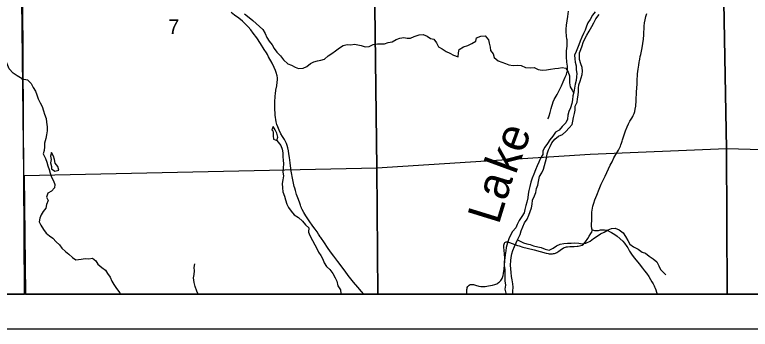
# Model space of a CAD drawing. Extents: x 0 to 34, y 0 to 22.
# Drawn here: x 4.117 to 6.214, y 14.287 to 15.182 of the extents above; entities that cross this region are included whole.
import ezdxf

# ---------------------------------------------------------------- set-up
doc = ezdxf.new("R2010")
doc.units = 0
for name, color, linetype in [('GM_X_County_Road_Text', 7, 'Continuous'), ('GM_X_Interchange_Ramps', 7, 'Continuous'), ('GM_X_Minor_River_Text', 7, 'Continuous'), ('GM_X_State_Location', 7, 'Continuous'), ('GM_X_State_Route', 7, 'Continuous'), ('GM_X_State_Shield', 7, 'Continuous'), ('GM_X_Unincorporated_Location', 7, 'Continuous'), ('SH_Data', 7, 'Continuous')]:
    doc.layers.add(name, color=color, linetype=linetype)

msp = doc.modelspace()

# ---------------------------------------------------------------- linework, layer by layer
at = {"layer": 'GM_X_County_Road_Text'}
for points in [[(4.772, 15.1846), (4.785, 15.1741), (4.7953, 15.1651), (4.8049, 15.1572), (4.8144, 15.1485), (4.8244, 15.1399), (4.8305, 15.1286), (4.8356, 15.1168), (4.8417, 15.1066), (4.8505, 15.0961), (4.8567, 15.0859), (4.864, 15.075), (4.8743, 15.0648), (4.8827, 15.0535), (4.8957, 15.0418), (4.906, 15.0378), (4.9167, 15.0321), (4.9262, 15.0288), (4.9387, 15.0297), (4.9492, 15.0347), (4.9598, 15.0428), (4.9696, 15.0481), (4.9798, 15.0509), (4.9896, 15.0525), (4.9998, 15.0552), (5.0103, 15.0644), (5.0205, 15.0713), (5.031, 15.079), (5.0431, 15.0875), (5.0533, 15.094), (5.0646, 15.0967), (5.0752, 15.0965), (5.0851, 15.0981), (5.0949, 15.0959), (5.1044, 15.094), (5.1162, 15.09), (5.1275, 15.0916), (5.1389, 15.0966), (5.1506, 15.099), (5.1612, 15.0987), (5.1711, 15.0991), (5.1809, 15.1023), (5.1926, 15.105), (5.2043, 15.1108), (5.2149, 15.1147), (5.2258, 15.1167), (5.2353, 15.1149), (5.2448, 15.1146), (5.2557, 15.1196), (5.2697, 15.125), (5.2815, 15.1255), (5.2925, 15.1203), (5.302, 15.1139), (5.3115, 15.1121), (5.3188, 15.1015), (5.325, 15.0906), (5.3356, 15.0846), (5.3467, 15.0775), (5.3573, 15.0722), (5.3672, 15.067), (5.3813, 15.0618), (5.3823, 15.0732), (5.3841, 15.0831), (5.3958, 15.09), (5.4087, 15.0939), (5.4196, 15.0997), (5.4313, 15.1062), (5.4327, 15.1161), (5.4456, 15.1212), (5.4581, 15.122), (5.4673, 15.1103), (5.4689, 15.1005), (5.472, 15.0899), (5.4728, 15.0804), (5.4805, 15.0702), (5.4836, 15.0604), (5.4951, 15.0506), (5.5156, 15.0432), (5.5251, 15.0391), (5.5377, 15.0369), (5.5498, 15.0382), (5.5608, 15.0368), (5.5733, 15.0316), (5.5858, 15.0305)], [(4.1378, 14.9976), (4.1377, 14.9995), (4.124, 15.0077), (4.1122, 15.0152), (4.1011, 15.028), (4.0953, 15.042), (4.0891, 15.0564), (4.0836, 15.0681), (4.0767, 15.0794), (4.0683, 15.0907), (4.0564, 15.1005), (4.0442, 15.1083), (4.0336, 15.1131), (4.0229, 15.1172), (4.0107, 15.1228), (4.003, 15.1334), (3.9973, 15.1454), (3.993, 15.1587), (3.9891, 15.1708)], [(5.5858, 15.0305), (5.5976, 15.0314), (5.6094, 15.0254), (5.62, 15.024), (5.6325, 15.0252), (5.6442, 15.0272), (5.6567, 15.0288), (5.6669, 15.0301), (5.6771, 15.0317), (5.6874, 15.0298), (5.6947, 15.0181), (5.6986, 15.0083), (5.6983, 14.9984), (5.698, 14.9878), (5.7004, 14.9768), (5.7054, 14.9666), (5.7101, 14.9603)], [(4.1377, 14.9995), (4.1535, 14.9962), (4.1634, 14.9856), (4.1696, 14.9747), (4.1757, 14.9645), (4.18, 14.9535), (4.1835, 14.9425), (4.1897, 14.9312), (4.1955, 14.9203), (4.1986, 14.9085), (4.2021, 14.8983), (4.206, 14.8862), (4.2076, 14.876), (4.2093, 14.8627), (4.2097, 14.8513), (4.2072, 14.8399), (4.2054, 14.8297), (4.2021, 14.8164), (4.2014, 14.8054), (4.2008, 14.7951), (4.1982, 14.7856), (4.2044, 14.7728), (4.2083, 14.7618), (4.211, 14.7516), (4.2149, 14.741), (4.2177, 14.7304), (4.2219, 14.7194), (4.2277, 14.7092), (4.2312, 14.6986), (4.2302, 14.6891), (4.2215, 14.6796), (4.211, 14.6738), (4.2073, 14.6624), (4.2119, 14.6526), (4.2079, 14.6419), (4.2053, 14.6316), (4.1982, 14.6221), (4.1926, 14.6122), (4.1885, 14.6027), (4.1867, 14.5928), (4.1913, 14.5826), (4.199, 14.5701), (4.2067, 14.56), (4.2163, 14.5524), (4.2258, 14.5461), (4.2346, 14.5359), (4.2441, 14.5269), (4.2507, 14.5171), (4.2614, 14.5084), (4.2713, 14.5005), (4.2816, 14.4908), (4.2915, 14.4844), (4.3059, 14.4864), (4.3176, 14.4884), (4.3282, 14.4874), (4.3381, 14.4886), (4.3476, 14.4815), (4.3542, 14.4717), (4.3656, 14.4623), (4.3759, 14.4551), (4.3813, 14.4453), (4.389, 14.4348), (4.3936, 14.4234), (4.3998, 14.4136), (4.4074, 14.4027), (4.4167, 14.3906), (4.4188, 14.3866)], [(4.864, 14.8242), (4.8751, 14.8099), (4.8794, 14.7989), (4.8814, 14.7883), (4.8811, 14.7777), (4.8823, 14.7678), (4.8828, 14.7576), (4.8821, 14.7458), (4.8811, 14.734), (4.8827, 14.7231), (4.8809, 14.7117), (4.8795, 14.7018), (4.8804, 14.6889), (4.8809, 14.6775), (4.8859, 14.665), (4.8883, 14.6548), (4.8929, 14.6427), (4.8976, 14.6329), (4.9045, 14.6223), (4.9137, 14.6125), (4.9255, 14.605), (4.9369, 14.5941), (4.9454, 14.584), (4.9549, 14.5749), (4.9546, 14.5632), (4.9581, 14.5533), (4.9655, 14.5397), (4.9724, 14.5269), (4.9782, 14.5167), (4.9832, 14.5061), (4.989, 14.4963), (4.9951, 14.4865), (4.9994, 14.4755), (5.0056, 14.465), (5.0155, 14.4571), (5.0235, 14.445), (5.0301, 14.4329), (5.0347, 14.4231), (5.0383, 14.4106), (5.0459, 14.3989), (5.0468, 14.3883), (5.0476, 14.3866)], [(5.5498, 14.5411), (5.5669, 14.533), (5.5764, 14.5297), (5.5858, 14.5282), (5.5957, 14.5245), (5.6079, 14.5212), (5.6178, 14.519), (5.6288, 14.5145), (5.6406, 14.5116), (5.6515, 14.5174), (5.6613, 14.5243), (5.6719, 14.5286), (5.6825, 14.5305), (5.693, 14.5318), (5.7033, 14.5319), (5.7135, 14.5323), (5.7245, 14.5313), (5.734, 14.5298), (5.7453, 14.5318), (5.757, 14.5372), (5.7668, 14.5449), (5.777, 14.5511), (5.7868, 14.5583), (5.7973, 14.5634), (5.8083, 14.5699), (5.8181, 14.5734), (5.8287, 14.5742), (5.8397, 14.5698), (5.8512, 14.5608), (5.8577, 14.551), (5.865, 14.5396), (5.8704, 14.5291), (5.8807, 14.5208), (5.894, 14.5145), (5.9051, 14.5062), (5.9146, 14.5036), (5.9257, 14.4946), (5.9367, 14.4875), (5.9474, 14.4785), (5.9528, 14.4675), (5.9575, 14.4566), (5.967, 14.4468), (5.9724, 14.4419)], [(4.6398, 14.3866), (4.6356, 14.3951), (4.6313, 14.408), (4.6282, 14.4197), (4.6269, 14.433), (4.6284, 14.4425), (4.6294, 14.4527), (4.6282, 14.4622), (4.6307, 14.4728), (4.6304, 14.4728)]]:
    msp.add_lwpolyline(points, dxfattribs=at)
at = {"layer": 'GM_X_Interchange_Ramps'}
for points in [[(5.1119, 14.3866), (5.1054, 14.3945), (5.0952, 14.4062), (5.083, 14.4203), (5.0714, 14.4348), (5.0677, 14.4398), (5.0585, 14.4522), (5.0382, 14.4797), (5.0268, 14.4944), (5.0174, 14.5068), (5.0083, 14.5194), (4.9995, 14.5322), (4.9893, 14.5475), (4.9875, 14.5501), (4.9843, 14.5548), (4.9825, 14.5576), (4.9787, 14.5636), (4.9728, 14.5717), (4.9669, 14.5799), (4.956, 14.5955), (4.9469, 14.6091), (4.9411, 14.6189), (4.9361, 14.6278), (4.9346, 14.6311), (4.934, 14.6325), (4.9326, 14.636), (4.9312, 14.6399), (4.9294, 14.6455), (4.9257, 14.6555), (4.9205, 14.6701), (4.9168, 14.682), (4.9151, 14.688), (4.9136, 14.6931), (4.9113, 14.7024), (4.9092, 14.7121), (4.905, 14.7361), (4.9018, 14.7604), (4.8998, 14.7759), (4.8984, 14.7857), (4.897, 14.7946), (4.8954, 14.803), (4.8936, 14.8094), (4.8913, 14.8155), (4.889, 14.8206), (4.8854, 14.8269), (4.8802, 14.8351), (4.8753, 14.8432), (4.8703, 14.8537), (4.8668, 14.8625), (4.8642, 14.8694), (4.8624, 14.8771), (4.8612, 14.8833), (4.8602, 14.8897), (4.8594, 14.8959), (4.8589, 14.903), (4.8585, 14.9115), (4.8583, 14.914), (4.8582, 14.926), (4.8586, 14.9383), (4.859, 14.9445), (4.8594, 14.9507), (4.8599, 14.9568), (4.8612, 14.9673), (4.8636, 14.9795), (4.8652, 14.9896), (4.8656, 14.9969), (4.8656, 14.9998), (4.8656, 15.0024), (4.865, 15.0074), (4.8624, 15.0174), (4.8606, 15.0227), (4.8566, 15.0314), (4.8504, 15.0441), (4.8407, 15.0622), (4.837, 15.0684), (4.8341, 15.0733), (4.8283, 15.083), (4.8178, 15.0994), (4.8069, 15.1159), (4.797, 15.1295), (4.7902, 15.1388), (4.7825, 15.1474), (4.7758, 15.154), (4.7665, 15.1633), (4.7554, 15.1723), (4.7437, 15.1804), (4.7343, 15.1878)], [(5.6367, 14.8857), (5.638, 14.8885), (5.6403, 14.8943), (5.643, 14.9032), (5.6459, 14.9152), (5.6476, 14.9212), (5.6496, 14.9276), (5.6519, 14.934), (5.6545, 14.9404), (5.663, 14.9549), (5.6696, 14.9678), (5.6753, 14.9794), (5.6805, 14.9906), (5.6862, 15.0036), (5.6893, 15.0117), (5.6911, 15.017), (5.6924, 15.0211), (5.693, 15.026), (5.6924, 15.035), (5.6907, 15.0471), (5.6897, 15.0618), (5.6896, 15.0728), (5.69, 15.0791), (5.6915, 15.0924), (5.6918, 15.104), (5.6915, 15.108), (5.6913, 15.1104), (5.691, 15.113), (5.6897, 15.1212), (5.6885, 15.1343), (5.6885, 15.1379), (5.6886, 15.1409), (5.6899, 15.1523), (5.6917, 15.164), (5.6934, 15.1767), (5.6955, 15.1918)], [(5.764, 14.5698), (5.7624, 14.5727), (5.7616, 14.5753), (5.7614, 14.5775), (5.7613, 14.5847), (5.7617, 14.5971), (5.7618, 14.6094), (5.7619, 14.6155), (5.7621, 14.6196), (5.7627, 14.6255), (5.7634, 14.6308), (5.7648, 14.6368), (5.7674, 14.6458), (5.7707, 14.6545), (5.7761, 14.6682), (5.783, 14.6857), (5.7889, 14.6996), (5.7924, 14.7069), (5.7997, 14.7223), (5.8046, 14.7326), (5.8098, 14.7435), (5.8146, 14.7536), (5.8195, 14.7634), (5.8249, 14.7743), (5.8377, 14.796), (5.8411, 14.8024), (5.8432, 14.8074), (5.8449, 14.8116), (5.8465, 14.8167), (5.8481, 14.8219), (5.8491, 14.8253), (5.8503, 14.8289), (5.8547, 14.8425), (5.8578, 14.8512), (5.8625, 14.8627), (5.8664, 14.871), (5.8707, 14.8791), (5.8755, 14.887), (5.8787, 14.8923), (5.8802, 14.8951), (5.8826, 14.9008), (5.8846, 14.9067), (5.8859, 14.9127), (5.8871, 14.922), (5.8881, 14.9375), (5.8896, 14.9623), (5.8908, 14.9839), (5.8912, 14.99), (5.8915, 14.9961), (5.892, 15.0095), (5.8925, 15.0139), (5.8942, 15.0272), (5.8959, 15.0378), (5.8973, 15.0468), (5.8979, 15.0504), (5.8988, 15.0554), (5.9001, 15.063), (5.9016, 15.069), (5.9052, 15.0872), (5.9073, 15.0995), (5.909, 15.1118), (5.9101, 15.1242), (5.9111, 15.149), (5.9121, 15.1583), (5.9138, 15.1674), (5.9159, 15.1765), (5.9186, 15.1854)], [(5.4058, 14.3866), (5.4058, 14.3962), (5.406, 14.3996), (5.4063, 14.4024), (5.407, 14.4055), (5.4082, 14.4083), (5.4101, 14.4107), (5.4126, 14.4125), (5.4154, 14.4137), (5.4184, 14.4142), (5.4215, 14.4142), (5.4246, 14.4137), (5.4306, 14.4121), (5.4396, 14.4095), (5.4457, 14.4084), (5.4518, 14.408), (5.458, 14.4084), (5.4671, 14.4099), (5.4792, 14.4123), (5.4852, 14.414), (5.4881, 14.415), (5.4909, 14.4163), (5.4936, 14.4177), (5.4962, 14.4194), (5.4987, 14.4213), (5.5009, 14.4234), (5.5029, 14.4257), (5.5047, 14.4282), (5.5062, 14.4309), (5.5075, 14.4337), (5.5085, 14.4366), (5.5094, 14.4396), (5.5106, 14.4457), (5.5122, 14.458), (5.5134, 14.4703), (5.5139, 14.4797), (5.5139, 14.489), (5.5131, 14.5014), (5.5122, 14.5106), (5.511, 14.5199), (5.5108, 14.523), (5.5109, 14.5261), (5.5116, 14.5291), (5.5131, 14.5317), (5.5144, 14.5333), (5.5162, 14.5344), (5.5182, 14.535), (5.5213, 14.5353), (5.5243, 14.5349), (5.5273, 14.534), (5.5505, 14.5251), (5.5549, 14.5237), (5.5653, 14.5207), (5.5776, 14.5175), (5.5973, 14.5123), (5.6313, 14.5034), (5.6374, 14.502), (5.6404, 14.5015), (5.6438, 14.5011), (5.6466, 14.5012), (5.6497, 14.5014), (5.6527, 14.502), (5.6555, 14.5027), (5.6582, 14.5036), (5.6617, 14.5053), (5.668, 14.5088), (5.6759, 14.5143), (5.6802, 14.5173), (5.683, 14.5191), (5.6868, 14.5204), (5.6898, 14.521), (5.6929, 14.5215), (5.699, 14.5221), (5.705, 14.5224), (5.708, 14.5224), (5.7111, 14.5225), (5.7201, 14.5229), (5.7231, 14.5232), (5.7271, 14.5237), (5.7308, 14.5247), (5.7346, 14.5262), (5.7382, 14.5287), (5.7435, 14.5358), (5.7507, 14.5454), (5.7547, 14.5517), (5.7594, 14.5591), (5.761, 14.5618), (5.7618, 14.5632), (5.7624, 14.5645), (5.7631, 14.5663), (5.764, 14.5698)], [(5.764, 14.5698), (5.7663, 14.569), (5.7696, 14.5681), (5.7748, 14.5676), (5.7777, 14.5676), (5.7791, 14.5678), (5.7808, 14.568), (5.7836, 14.5686), (5.7866, 14.5692), (5.7885, 14.5694), (5.7906, 14.5696), (5.7943, 14.5697), (5.7982, 14.5694), (5.8043, 14.5682), (5.8093, 14.5664), (5.8108, 14.5658), (5.8125, 14.565), (5.8182, 14.5619), (5.8272, 14.5567), (5.8344, 14.5516), (5.8502, 14.537), (5.8546, 14.5314), (5.8619, 14.5224), (5.8649, 14.5181), (5.8695, 14.5089), (5.873, 14.5036), (5.8773, 14.4978), (5.8838, 14.489), (5.8973, 14.4728), (5.9067, 14.4603), (5.9125, 14.4529), (5.918, 14.4459), (5.9244, 14.4365), (5.9295, 14.4286), (5.9332, 14.422), (5.9366, 14.4156), (5.9392, 14.4105), (5.9408, 14.4073), (5.9424, 14.4032), (5.944, 14.3985), (5.9461, 14.392), (5.9477, 14.3866)]]:
    msp.add_lwpolyline(points, dxfattribs=at)
at = {"layer": 'GM_X_Minor_River_Text'}
for points in [[(4.864, 14.8242), (4.8666, 14.8337), (4.8638, 14.8443), (4.8592, 14.8541), (4.8534, 14.8639), (4.8497, 14.8544), (4.8528, 14.851)], [(4.8528, 14.851), (4.8532, 14.8469), (4.854, 14.8374), (4.8545, 14.8275), (4.864, 14.8242)], [(4.2398, 14.7495), (4.2322, 14.7593), (4.2302, 14.7696), (4.2274, 14.7794), (4.2213, 14.7896), (4.2187, 14.7797), (4.2207, 14.7699), (4.2193, 14.7604), (4.2213, 14.7501), (4.2221, 14.7433)], [(4.2221, 14.7433), (4.2313, 14.7362), (4.2422, 14.7397), (4.2398, 14.7495)]]:
    msp.add_lwpolyline(points, dxfattribs=at)
at = {"layer": 'GM_X_State_Route'}
msp.add_lwpolyline([(1.8602, 14.3866), (4.1451, 14.3866), (4.14, 15.2216), (4.132, 15.4174), (4.1252, 15.9611), (4.1251, 15.9712), (4.1206, 16.454), (4.1201, 16.507), (4.1149, 16.7255)], dxfattribs=at)
for points in [[(5.1364, 15.7406), (6.1276, 15.7926), (6.1462, 14.7998), (5.7574, 14.7844), (5.149, 14.7448)], [(6.1276, 15.7926), (7.1265, 15.7834), (7.1266, 15.779), (7.1286, 14.7729), (6.1462, 14.7998)], [(4.1315, 15.7198), (5.1364, 15.7406), (5.149, 14.7448), (4.1433, 14.7233), (4.1432, 14.7291)], [(5.1519, 14.3866), (6.1473, 14.3866), (6.1462, 14.7998), (5.7574, 14.7844), (5.149, 14.7448)], [(6.1473, 14.3866), (7.1397, 14.3866), (7.1286, 14.7729), (6.1462, 14.7998)], [(4.1472, 14.3866), (5.1519, 14.3866), (5.149, 14.7448), (4.1433, 14.7233)]]:
    msp.add_lwpolyline(points, close=True, dxfattribs=at)
at = {"layer": 'GM_X_State_Shield'}
for points in [[(5.7719, 15.1899), (5.7641, 15.1803), (5.757, 15.1685), (5.7502, 15.159), (5.7469, 15.1495), (5.7425, 15.138), (5.7384, 15.1282), (5.7336, 15.1179), (5.7287, 15.1068), (5.7247, 15.0965), (5.7206, 15.0867), (5.7169, 15.0768), (5.7124, 15.0669), (5.7133, 15.0562), (5.7145, 15.0464), (5.7169, 15.0362), (5.7174, 15.0252), (5.7194, 15.0146), (5.7179, 15.0051), (5.7173, 14.9948), (5.7147, 14.9845), (5.7122, 14.9728), (5.7104, 14.9617), (5.7082, 14.9507), (5.7068, 14.9397), (5.7046, 14.9291), (5.7009, 14.9169), (5.6965, 14.9062), (5.6939, 14.8956), (5.6925, 14.8842), (5.688, 14.8743), (5.6772, 14.8632), (5.6685, 14.8533), (5.6587, 14.8471)], [(5.6976, 14.8596), (5.7055, 14.8691), (5.7073, 14.8786), (5.7095, 14.8893), (5.7124, 14.9003), (5.7146, 14.9102), (5.7145, 14.9216), (5.7197, 14.9326), (5.7215, 14.9425), (5.7229, 14.9524), (5.724, 14.9634), (5.7243, 14.9732), (5.7253, 14.9827), (5.729, 14.9926), (5.7316, 15.0021), (5.7342, 15.012), (5.7352, 15.0215), (5.734, 15.0318), (5.7305, 15.0416), (5.7266, 15.0541), (5.7264, 15.073), (5.7301, 15.0826), (5.7346, 15.0932), (5.7371, 15.1027), (5.7416, 15.113), (5.7475, 15.1237), (5.7539, 15.1351), (5.7617, 15.1481), (5.7681, 15.1587), (5.7736, 15.1702), (5.7826, 15.1824)], [(5.6587, 14.8471), (5.6505, 14.8364), (5.6426, 14.8261), (5.6355, 14.8154), (5.6277, 14.8051), (5.6225, 14.7941), (5.6218, 14.7842), (5.6158, 14.7739), (5.611, 14.7621), (5.6062, 14.7515), (5.6017, 14.74), (5.5962, 14.7282), (5.5921, 14.7168), (5.5884, 14.705), (5.5851, 14.6925), (5.5826, 14.6815), (5.5808, 14.6712), (5.5797, 14.6602), (5.5768, 14.6488), (5.5735, 14.6385), (5.5709, 14.6275), (5.5695, 14.6176), (5.5628, 14.6073), (5.5549, 14.5959), (5.5493, 14.5852), (5.5453, 14.5753), (5.5359, 14.565), (5.5299, 14.5547), (5.5255, 14.5444), (5.5218, 14.533), (5.5177, 14.5193), (5.5171, 14.5098), (5.5145, 14.4988), (5.5135, 14.4893), (5.5124, 14.4791), (5.5125, 14.4673), (5.5141, 14.4571), (5.5138, 14.4468), (5.5143, 14.437), (5.5137, 14.4244), (5.5157, 14.4123), (5.5143, 14.4009), (5.517, 14.3896), (5.5172, 14.3866)], [(5.5367, 14.3866), (5.5367, 14.395), (5.5373, 14.406), (5.5368, 14.4163), (5.5345, 14.4269), (5.5325, 14.4371), (5.532, 14.4485), (5.5312, 14.4587), (5.5303, 14.4693), (5.5306, 14.4819), (5.5316, 14.4913), (5.5338, 14.5012), (5.5367, 14.5107), (5.5412, 14.5222), (5.546, 14.5324), (5.5509, 14.5435), (5.5572, 14.5564), (5.5601, 14.5671), (5.5657, 14.5778), (5.5698, 14.5892), (5.5776, 14.6002), (5.5824, 14.6113), (5.5858, 14.6219), (5.5898, 14.6318), (5.5916, 14.6425), (5.593, 14.6542), (5.5986, 14.6668), (5.6019, 14.6763), (5.6045, 14.687), (5.6078, 14.6968), (5.61, 14.7075), (5.6129, 14.7212), (5.6192, 14.7318), (5.6244, 14.7421), (5.6303, 14.7627), (5.6329, 14.7737), (5.6347, 14.7855), (5.638, 14.7973), (5.6428, 14.8072), (5.648, 14.8174), (5.6566, 14.8274), (5.6668, 14.8358), (5.6781, 14.8405), (5.6879, 14.8493), (5.6976, 14.8596)]]:
    msp.add_lwpolyline(points, dxfattribs=at)
at = {"layer": 'SH_Data'}
for points in [[(1.7602, 21.2866), (8.7602, 21.2866), (8.7602, 14.2866), (1.7602, 14.2866)], [(1.8602, 21.1866), (8.6602, 21.1866), (8.6602, 14.3866), (1.8602, 14.3866)]]:
    msp.add_lwpolyline(points, close=True, dxfattribs=at)

# ---------------------------------------------------------------- texts
at = {"layer": 'GM_X_State_Location'}
msp.add_text('7', height=0.0419, rotation=0, dxfattribs=at).set_placement((4.5545, 15.1265))
at = {"layer": 'GM_X_Unincorporated_Location'}
for s, height, rotation, p in [('ke', 0.09471, 69.8721, (5.5446, 14.7246)), ('La', 0.09472, 72.8721, (5.4964, 14.582))]:
    msp.add_text(s, height=height, rotation=rotation, dxfattribs=at).set_placement(p)

doc.saveas('drawing.dxf')
